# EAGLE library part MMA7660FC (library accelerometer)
3-Axis Orientation/Motion Detection Sensor Features Digital Output (I2C) 3mm x 3mm x 0.9mm DFN Package Low Power Current Consumption: Off Mode: 0.4 ?A, Standby Mode: 2 ?A, Active Mode: 47 ?A at 1 ODR Configurable Samples per Second from 1 to 120 samples a second. Low Voltage Operation: ? Analog Voltage: 2.4 V - 3.6 V ? Digital Voltage: 1.71 V - 3.6 V Auto-Wake/Sleep Feature for Low Power Consumption Tilt Orientation Detection for Portrait/Landscape Capability Gesture Detection Including Shake Detection and Tap
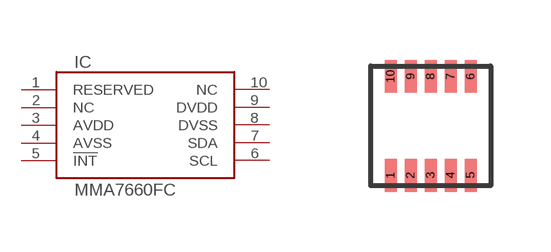
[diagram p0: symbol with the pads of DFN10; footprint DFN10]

Designator prefix IC

## MMA7660FC  [DFN10]
1  RESERVED
2  NC
3  AVDD
4  AVSS
5  !INT
6  SCL
7  SDA
8  DVSS
9  DVDD
10  NC

## MMA7660FC+  [DFN10]
Pads as for DFN10

## Footprint DFN10 (pad centres in mm)
smd 0.3 x 0.825: 1 -1,-1.24; 2 -0.5,-1.24; 3 0,-1.24; 4 0.5,-1.24; 5 1,-1.24; 6 1,1.24; 7 0.5,1.24; 8 0,1.24; 9 -0.5,1.24; 10 -1,1.24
